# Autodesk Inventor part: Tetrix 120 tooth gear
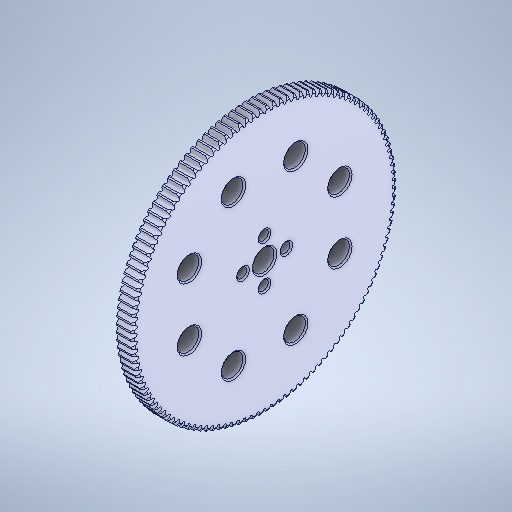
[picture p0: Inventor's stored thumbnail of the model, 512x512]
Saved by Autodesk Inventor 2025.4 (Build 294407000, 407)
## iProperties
Created: 2021-10
Part Number: Tetrix 120 tooth gear
Material: Genérico
Document SubType Name: Modeling
Designer: usuario
Density: 1 g/cm^3
Appearance: Valor por defecto
Author: usuario
Sending System: SolidWorks 2016
Last Author: LENOVO
Last Saved: 2021-10-22
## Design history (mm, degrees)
chamfer "Chamfer2"
node "Sólido1"
